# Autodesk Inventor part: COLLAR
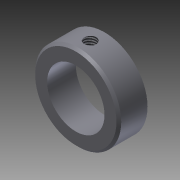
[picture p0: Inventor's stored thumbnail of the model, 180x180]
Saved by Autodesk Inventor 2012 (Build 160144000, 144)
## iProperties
Shininess: 64.0
Length Units: 11272
Angle Units: 11279
Time Units: 11290
Mass Units: 11286
Length Display Precision: 3
Angle Display Precision: 2
Compacted: True
Part Number: COLLAR
Document SubType Name: Modeling
Created: 2003-11
Designer: Autodesk, Inc.
Manufacturer: Standard
Standards Organization: Custom
Mass: 25.9974 g
Surface Area: 21.2895 cm^2
Volume: 3.30755 cm^3
Density: 7.86 g/cm^3
Material: Steel, Mild
Density: 0.0
Volumn: 0.0
Area: 0.0
PropertySet Name: Model Information
Control State: 0
Master: False
Checked Out: False
Author: Autodesk, Inc.
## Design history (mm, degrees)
sketch "Sketch1"
  geometry: C1 r 14.287 at (0, 0); C2 r 9.525 at (0, 0); 1 further point
  constraints: 2 centre point, 2 coincident
  dimensions: "d0" = 28.575 diameter of C1; "d1" = 19.05 diameter of C2
extrude "Extrusion1" new body sketch "Sketch1" distance "d2" = 9.525; taper "d3" = 0 deg
chamfer "Chamfer1" distance "d4" = 0.7874; stored, may be unused: second distance "d5" = 3.175, angle "d16" = 45 deg
sketch "Sketch3"
  geometry: L1 (-14.287, 0)-(14.287, 0) reference; L2 (14.287, 8.738)-(-14.287, 8.738) reference; L3 (14.287, 0)-(14.287, 8.738) reference; L4 (-14.287, 0)-(-14.287, 8.738) reference; L5 (0, 0)-(0, 8.738); 1 further point
  constraints: 2 end point, 2 midpoint, 1 point on line
  dimensions: "d8" = 4.7625 distance from line of L1 point (0, 4.763)
hole "Hole1" sketch "Sketch3" at (0, 4.763) diameter "d9" = 3.9624; stored, may be unused: countersink angle "d13" = 82 deg, drill point angle "d15" = 118 deg; dims "d10" = 12.7, "d11" = 9.525, "d12" = 6.35, "d14" = 19.05
body "Solid1"
